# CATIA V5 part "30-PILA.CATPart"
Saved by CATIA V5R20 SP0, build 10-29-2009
Part number: 30-PILA
Revision: ANY
Definition: UNKNOWN
Nomenclature: 30-PILA
Source: Unknown
Bounding box of the stored display mesh (mm): x 0 to 44.33, y 0 to 25, z -2.58 to 4
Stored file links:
  C:\Users\Utente\Desktop\IO LAVORO\3D X SITO CF\CUMSA\3D files CC\CCHS5328\30-PILA.CATPart
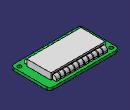
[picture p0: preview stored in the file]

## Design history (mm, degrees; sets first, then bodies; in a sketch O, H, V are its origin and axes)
Body1 "Saliente-Extruir6" (main body)
  Solid1: solid without history
Body2 "Cortar-Extruir3"
  Solid2: solid without history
